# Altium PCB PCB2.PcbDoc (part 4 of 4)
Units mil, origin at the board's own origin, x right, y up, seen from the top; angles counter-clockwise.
Board outline 7170.03 x 5785.03 mil, 4 copper layers (Top Layer, GND, PWR, Bottom Layer), stack 22.378 mil thick; 348 components, 320 nets, 1937 pads, 429 vias.
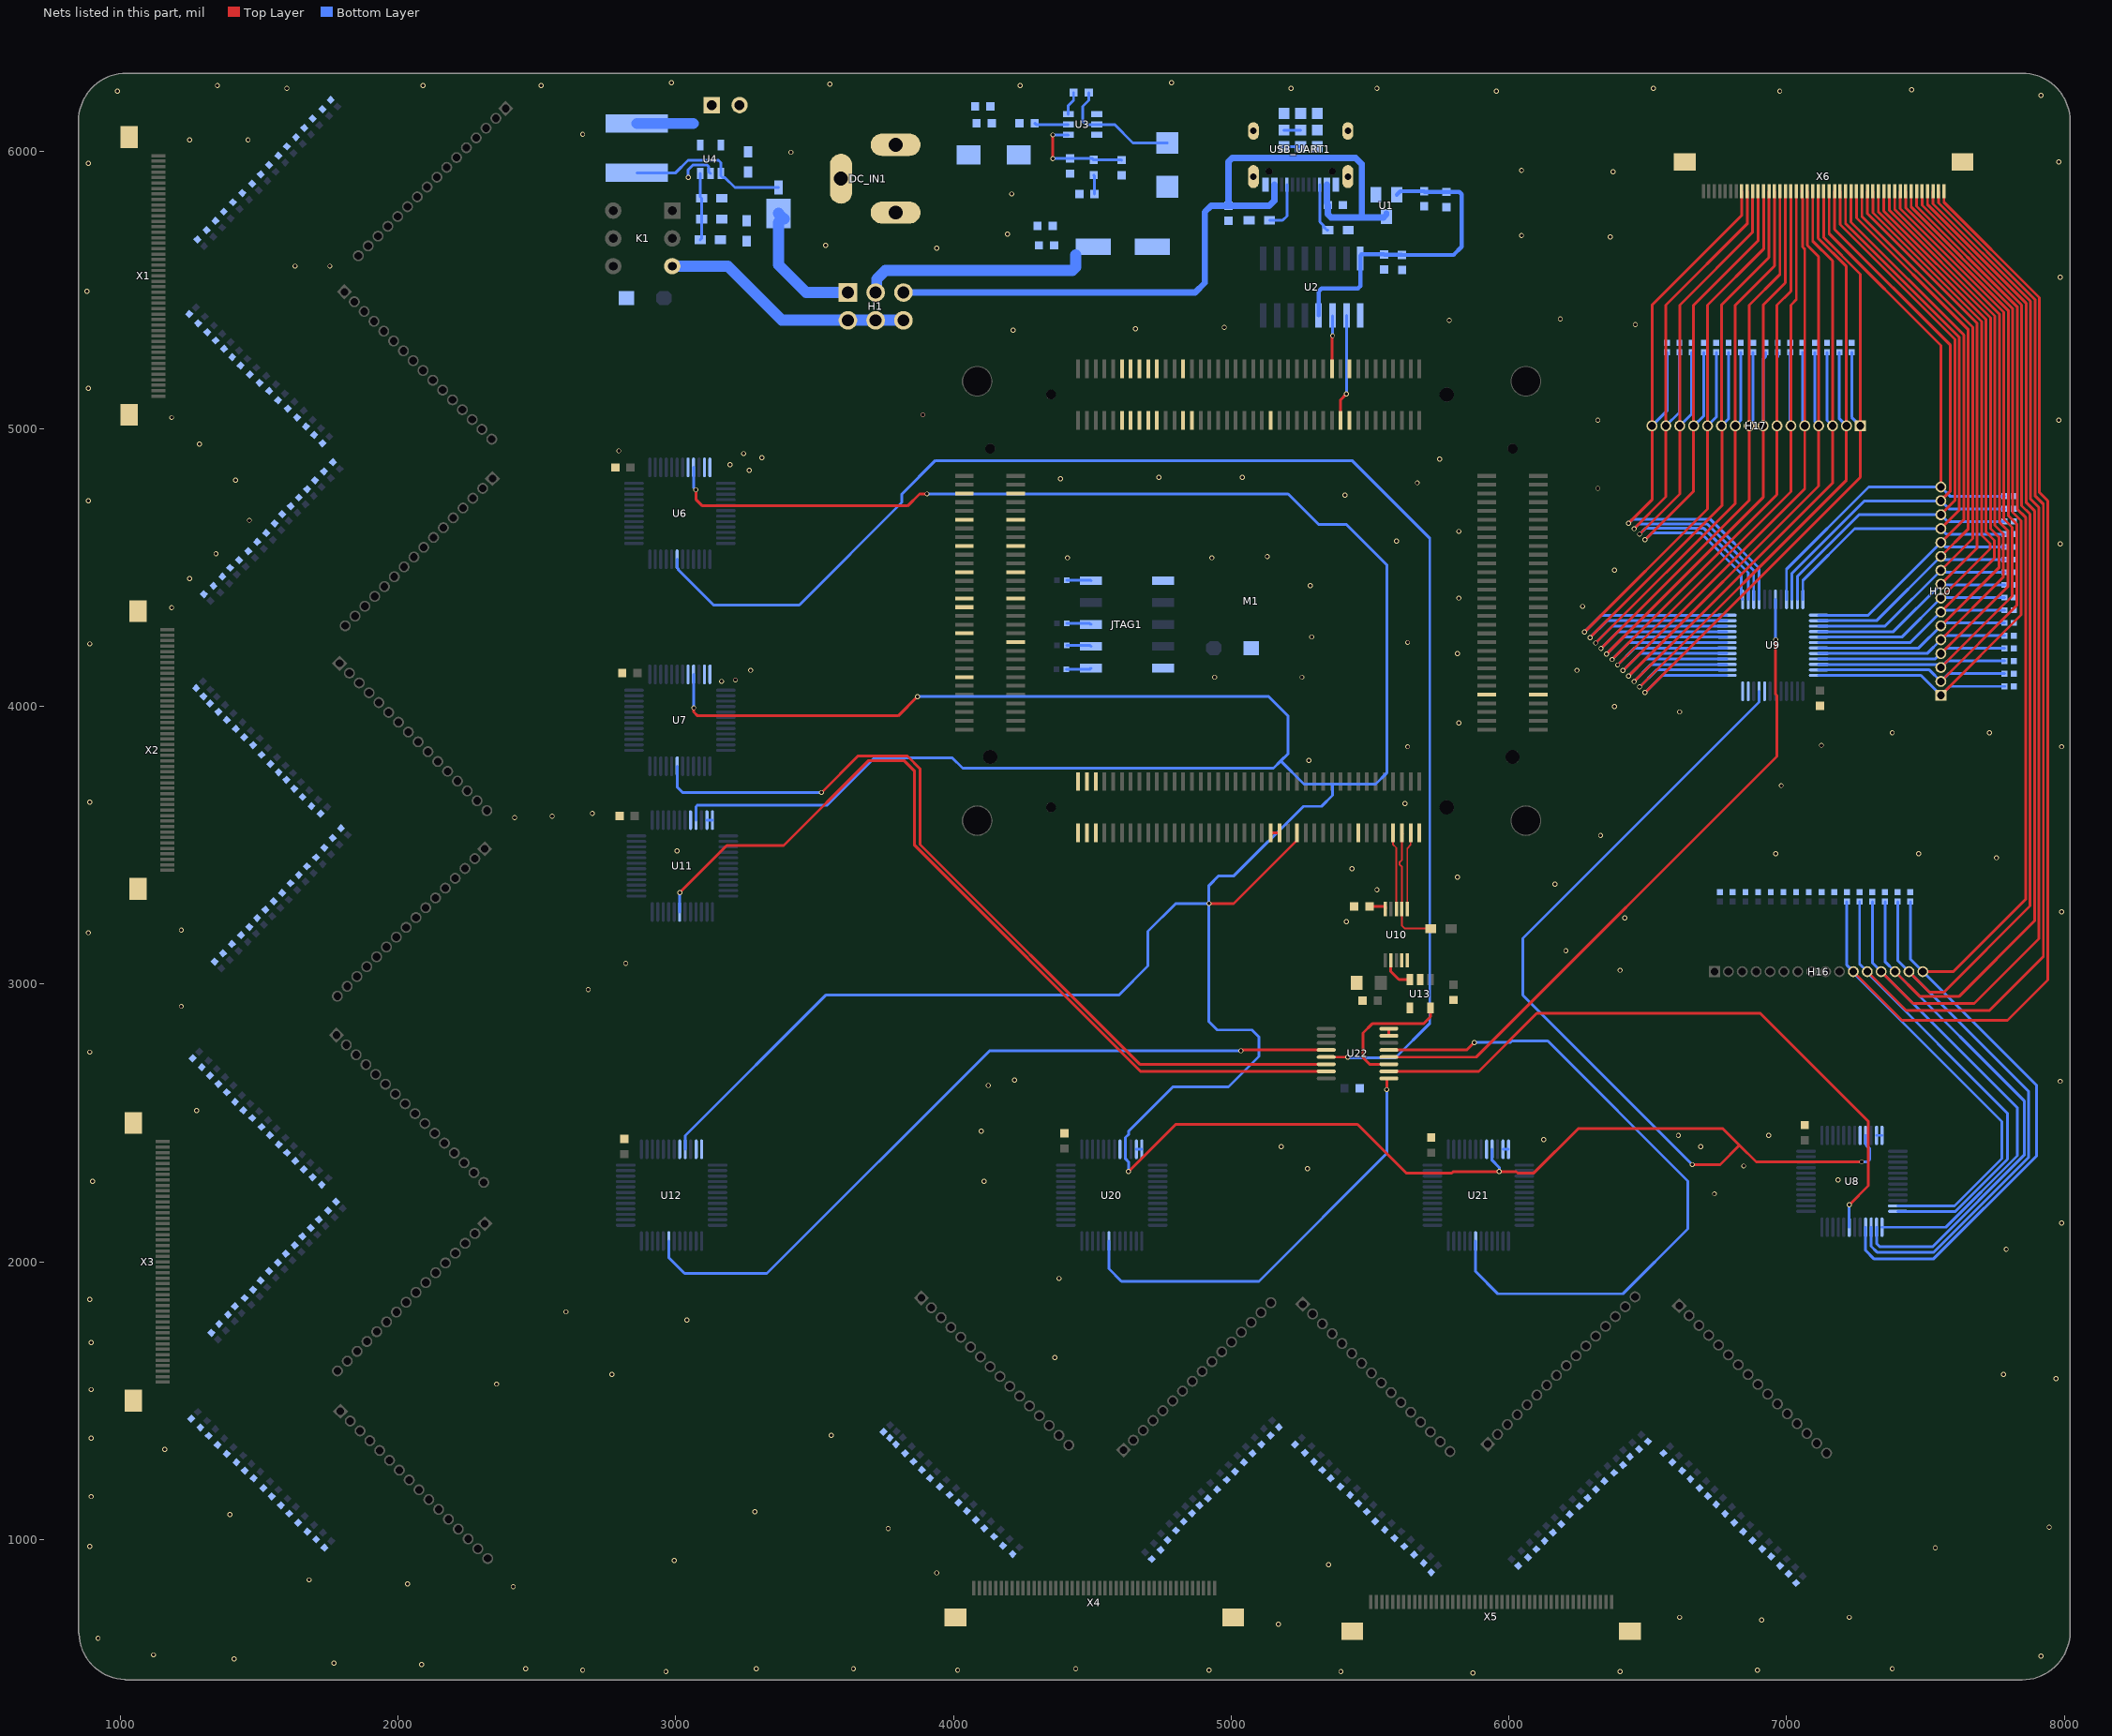
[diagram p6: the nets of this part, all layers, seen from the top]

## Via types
v1: diameter 18, hole 12, Top Layer to Bottom Layer, 429 vias

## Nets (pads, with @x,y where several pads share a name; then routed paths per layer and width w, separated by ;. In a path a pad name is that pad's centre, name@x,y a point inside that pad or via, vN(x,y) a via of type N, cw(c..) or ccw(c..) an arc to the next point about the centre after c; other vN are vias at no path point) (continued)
G218: H16.11 R194.2 U8.35 X6.1 | length 5428.8
  Top Layer w10: H16.11@7240,3045 7415,2870 7795,2870 7940,3015 7940,4740 7909.69,4770.31 7909.69,5472.1 7566.18,5815.6 X6.1@7566.18,5855
  Bottom Layer w10: R194.2@7216.75,3296.87 7216.75,3068.25 H16.11@7240,3045 7240,3039.77 7775,2504.77 7775,2372 7604.42,2201.42 U8.35@7400.36,2201.42
G219: H16.12 R196.2 U8.36 X6.2 | length 5305.2
  Top Layer w10: H16.12@7290,3045 7430,2905 7730,2905 7924,3099 7924,4728.17 7893.69,4758.48 7893.69,5465.47 7546.5,5812.66 X6.2@7546.5,5855.06
  Bottom Layer w10: R196.2@7262.44,3296.87 7262.44,3072.56 H16.12@7290,3045 7290,3040 7795,2535 7795,2369.37 7607.36,2181.73 U8.36@7400.36,2181.73
G220: H16.13 R198.2 U8.37 X6.3 | length 5286.6
  Top Layer w10: H16.13@7340,3045 7455,2930 7675,2930 7908,3163 7908,4716.32 7877.69,4746.64 7877.69,5458.84 7526.81,5809.72 X6.3@7526.81,5855
  Bottom Layer w10: R198.2@7308.14,3296.87 7308.14,3076.86 H16.13@7340,3045 7830,2555 7830,2381.74 7572.9,2124.64 U8.37@7343.27,2124.64
G221: H16.14 R200.2 U8.38 X6.4 | length 5290.4
  Top Layer w10: H16.14@7390,3045 7480,2955 7620,2955 7892,3227 7892,4704.49 7861.69,4734.81 7861.69,5452.22 7507.13,5806.77 X6.4@7507.13,5855
  Bottom Layer w10: U8.38@7323.58,2124.64 7323.58,2066.42 7335,2055 7525.89,2055 7855,2384.11 7855,2580 H16.14@7390,3045 7353.83,3081.17 R200.2@7353.83,3296.87
G222: H16.15 R202.2 U8.39 X6.5 | length 5231.8
  Top Layer w10: H16.15@7440,3045 7514,2971 7566,2971 7876,3281 7876,4692.64 7845.69,4722.96 7845.69,5445.59 7487.44,5803.83 X6.5@7487.44,5855
  Bottom Layer w10: U8.39@7303.9,2124.64 7303.9,2056.1 7325,2035 7530,2035 7871,2376 7871,2614 H16.15@7440,3045 7399.52,3085.48 R202.2@7399.52,3296.87
G223: H16.16 R204.2 U8.40 X6.6 | length 5159.7
  Top Layer w10: X6.6@7467.76,5855 7467.76,5800.89 7829.69,5438.96 7829.69,4711.13 7860,4680.81 7860,3305 7600,3045 H16.16@7490,3045
  Bottom Layer w10: U8.40@7284.21,2124.64 7284.21,2040.79 7315,2010 7527.63,2010 7900,2382.37 7900,2635 H16.16@7490,3045 7445.21,3089.79 R204.2@7445.21,3296.87
G224: H10.1 R206.2 U9.12 X6.7 | length 2810.4
  Top Layer w10: X6.7@7448.07,5855 7448.07,5797.95 7813.69,5432.33 7813.69,4699.28 7844,4668.97 7844,4329 H10.1@7555,4040
  Bottom Layer w10: U9.12@7115.36,4111.73 7483.27,4111.73 H10.1@7555,4040 7587.04,4072.04 R206.2@7784.05,4072.04
G225: H10.2 R208.2 U9.11 X6.8 | length 2740.9
  Top Layer w10: X6.8@7428.39,5855 7428.39,5795 7797.69,5425.71 7797.69,4687.45 7828,4657.14 7828,4363 H10.2@7555,4090
  Bottom Layer w10: U9.11@7115.36,4131.42 7513.58,4131.42 H10.2@7555,4090 7582.7,4117.7 R208.2@7784.05,4117.7
G226: H10.3 R210.2 U9.10 X6.9 | length 2671.5
  Top Layer w10: X6.9@7408.7,5855 7408.7,5792.06 7781.69,5419.08 7781.69,4675.6 7812,4645.29 7812,4397 H10.3@7555,4140
  Bottom Layer w10: U9.10@7115.36,4151.1 7543.9,4151.1 H10.3@7555,4140 7578.37,4163.37 R210.2@7784.05,4163.37
G227: H10.4 R212.2 U9.9 X6.10 | length 2617.9
  Top Layer w10: X6.10@7389.02,5855 7389.02,5789.12 7765.69,5412.45 7765.69,4663.77 7796,4633.46 7796,4431 H10.4@7555,4190
  Bottom Layer w10: U9.9@7115.36,4170.79 7534.46,4170.79 7553.67,4190 H10.4@7555,4190 7574.04,4209.04 R212.2@7784.05,4209.04
G228: H10.5 R214.2 U9.8 X6.11 | length 2573.6
  Top Layer w10: X6.11@7369.33,5855 7369.33,5786.18 7749.69,5405.82 7749.69,4651.93 7780,4621.61 7780,4465 H10.5@7555,4240
  Bottom Layer w10: U9.8@7115.36,4190.47 7505.47,4190.47 H10.5@7555,4240 7569.7,4254.7 R214.2@7784.05,4254.7
G229: H10.6 R216.2 U9.7 X6.12 | length 2529.3
  Top Layer w10: X6.12@7349.65,5855 7349.65,5783.23 7733.69,5399.2 7733.69,4640.1 7764,4609.78 7764,4499 H10.6@7555,4290
  Bottom Layer w10: U9.7@7115.36,4210.16 7475.16,4210.16 H10.6@7555,4290 7565.37,4300.37 R216.2@7784.05,4300.37
G230: H10.7 R218.2 U9.6 X6.13 | length 2484.9
  Top Layer w10: X6.13@7329.96,5855 7329.96,5780.29 7717.69,5392.57 7717.69,4628.25 7748,4597.93 7748,4533 H10.7@7555,4340
  Bottom Layer w10: U9.6@7115.36,4229.84 7444.84,4229.84 H10.7@7555,4340 7561.04,4346.04 R218.2@7784.05,4346.04
G231: H10.8 R220.2 U9.5 X6.14 | length 2440.6
  Top Layer w10: X6.14@7310.28,5855 7310.28,5777.35 7701.69,5385.94 7701.69,4616.42 7732,4586.1 7732,4567 H10.8@7555,4390
  Bottom Layer w10: U9.5@7115.36,4249.53 7414.53,4249.53 H10.8@7555,4390 7556.7,4391.7 R220.2@7784.05,4391.7
G232: H10.9 R222.2 U9.4 X6.15 | length 2373.3
  Top Layer w10: X6.15@7290.59,5855 7290.59,5774.41 7685.69,5379.31 7685.69,4570.69 H10.9@7555,4440
  Bottom Layer w10: U9.4@7115.36,4269.21 7384.21,4269.21 H10.9@7555,4440 7557.63,4437.37 R222.2@7784.05,4437.37
G233: H10.10 R224.2 U9.3 X6.16 | length 2332.6
  Top Layer w10: X6.16@7270.91,5855 7270.91,5764.09 7669.69,5365.31 7669.69,4604.69 H10.10@7555,4490
  Bottom Layer w10: U9.3@7115.36,4288.9 7353.9,4288.9 H10.10@7555,4490 7561.96,4483.04 R224.2@7784.05,4483.04
G234: H10.11 R226.2 U9.2 X6.17 | length 2291.8
  Top Layer w10: X6.17@7251.22,5855 7251.22,5758.78 7653.69,5356.31 7653.69,4638.69 H10.11@7555,4540
  Bottom Layer w10: U9.2@7115.36,4308.58 7323.58,4308.58 H10.11@7555,4540 7566.3,4528.7 R226.2@7784.05,4528.7
G235: H10.12 R228.2 U9.1 X6.18 | length 2251.1
  Top Layer w10: X6.18@7231.54,5855 7231.54,5743.46 7637.69,5337.31 7637.69,4672.69 H10.12@7555,4590
  Bottom Layer w10: U9.1@7115.36,4328.27 7293.27,4328.27 H10.12@7555,4590 7570.63,4574.37 R228.2@7784.05,4574.37
G236: H10.13 R230.2 U9.48 X6.19 | length 2291.7
  Top Layer w10: X6.19@7211.85,5855 7211.85,5738.15 7621.69,5328.31 7621.69,4707.63 7555,4640.95 H10.13@7555,4640
  Bottom Layer w10: U9.48@7058.27,4385.36 7058.27,4453.27 7245,4640 H10.13@7555,4640 7574.96,4620.04 R230.2@7784.05,4620.04
G237: H10.14 R232.2 U9.47 X6.20 | length 2287.8
  Top Layer w10: X6.20@7192.17,5855 7192.17,5735.2 7605.69,5321.69 7605.69,4741.63 7555,4690.95 H10.14@7555,4690
  Bottom Layer w10: U9.47@7038.58,4385.36 7038.58,4468.58 7260,4690 H10.14@7555,4690 7579.3,4665.7 R232.2@7784.05,4665.7
G238: H10.15 R234.2 U9.46 X6.21 | length 2285.5
  Top Layer w10: X6.21@7172.48,5855 7172.48,5717.52 7589.69,5300.31 7589.69,4775.63 7569.37,4755.31 7561.48,4755.31 7561.48,4746.48 H10.15@7555,4740
  Bottom Layer w10: U9.46@7018.9,4385.36 7018.9,4478.9 7280,4740 H10.15@7555,4740 7583.63,4711.37 R234.2@7784.05,4711.37
G239: H10.16 R236.2 U9.45 X6.22 | length 2261.5
  Top Layer w10: X6.22@7152.8,5855 7152.8,5702.2 7555,5300 H10.16@7555,4790
  Bottom Layer w10: U9.45@6999.21,4385.36 6999.21,4494.21 7295,4790 H10.16@7555,4790 7587.96,4757.04 R236.2@7784.05,4757.04
G240: H17.1 R238.2 U9.25 X6.23 | length 2778.6
  Top Layer w10: v1(6490,4050) 7265,4825 H17.1@7265,5010 7265,5556.55 7133.11,5688.44 X6.23@7133.11,5855
  Bottom Layer w10: v1(6490,4050) 6551.73,4111.73 U9.25@6784.64,4111.73 ; R238.2@7233.96,5274.85 7233.96,5041.04 H17.1@7265,5010
G241: H17.2 R240.2 U9.26 X6.24 | length 2751.1
  Top Layer w10: v1(6470.2,4069.8) 7215,4814.6 H17.2@7215,5010 7215,5583.92 7113.43,5685.49 X6.24@7113.43,5855
  Bottom Layer w10: v1(6470.2,4069.8) 6531.82,4131.42 U9.26@6784.64,4131.42 ; R240.2@7189.63,5274.85 7189.63,5035.37 H17.2@7215,5010
G242: H17.3 R242.2 U9.27 X6.25 | length 2723.6
  Top Layer w10: v1(6450.4,4089.6) 7165,4804.19 H17.3@7165,5010 7165,5604.08 7093.74,5675.33 X6.25@7093.74,5855
  Bottom Layer w10: v1(6450.4,4089.6) 6511.9,4151.1 U9.27@6784.64,4151.1 ; R242.2@7145.3,5274.85 7145.3,5029.7 H17.3@7165,5010
G243: H17.4 R244.2 U9.28 X6.26 | length 2696.2
  Top Layer w10: v1(6430.6,4109.4) 7115,4793.79 H17.4@7115,5010 7115,5619.24 7074.06,5660.17 X6.26@7074.06,5855
  Bottom Layer w10: v1(6430.6,4109.4) 6492,4170.79 U9.28@6784.64,4170.79 ; R244.2@7100.96,5274.85 7100.96,5024.04 H17.4@7115,5010
G244: H17.5 R246.2 U9.29 X6.27 | length 2668.7
  Top Layer w10: v1(6410.8,4129.2) 7065,4783.39 H17.5@7065,5010 7065,5646.61 7057.15,5654.45 7057.15,5828.55 7055.28,5830.43 7055.28,5854.09 X6.27@7054.37,5855
  Bottom Layer w10: v1(6410.8,4129.2) 6472.08,4190.47 U9.29@6784.64,4190.47 ; R246.2@7056.63,5274.85 7056.63,5018.37 H17.5@7065,5010
G245: H17.6 R248.2 U9.30 X6.28 | length 2657.6
  Top Layer w10: v1(6391.01,4148.99) 7015,4772.99 H17.6@7015,5010 7015,5445 7034.69,5464.69 X6.28@7034.69,5855
  Bottom Layer w10: v1(6391.01,4148.99) 6452.17,4210.16 U9.30@6784.64,4210.16 ; R248.2@7012.3,5274.85 7012.3,5012.7 H17.6@7015,5010
G246: H17.7 R250.2 U9.31 X6.29 | length 2657.7
  Top Layer w10: v1(6371.21,4168.79) 6965,4762.59 H17.7@6965,5010 6965,5445 7015,5495 X6.29@7015,5855
  Bottom Layer w10: v1(6371.21,4168.79) 6432.25,4229.84 U9.31@6784.64,4229.84 ; H17.7@6965,5010 6965,5255.75 6967.96,5258.72 R250.2@6967.96,5274.85
G247: H17.8 R252.2 U9.32 X6.30 | length 2660
  Top Layer w10: v1(6351.41,4188.59) 6915,4752.19 H17.8@6915,5010 6915,5445 6995.32,5525.32 X6.30@6995.32,5855
  Bottom Layer w10: v1(6351.41,4188.59) 6412.34,4249.53 U9.32@6784.64,4249.53 ; H17.8@6915,5010 6915,5250.09 6923.63,5258.72 R252.2@6923.63,5274.85
G248: H17.9 R254.2 U9.33 X6.31 | length 2662.4
  Top Layer w10: v1(6331.61,4208.39) 6865,4741.78 H17.9@6865,5010 6865,5445 6975.63,5555.63 X6.31@6975.63,5855
  Bottom Layer w10: v1(6331.61,4208.39) 6392.43,4269.21 U9.33@6784.64,4269.21 ; H17.9@6865,5010 6879.3,5024.3 R254.2@6879.3,5274.85
G249: H17.10 R256.2 U9.34 X6.32 | length 2664.7
  Top Layer w10: v1(6311.81,4228.19) 6815,4731.38 H17.10@6815,5010 6815,5445 6955.95,5585.95 X6.32@6955.95,5855
  Bottom Layer w10: v1(6311.81,4228.19) 6372.52,4288.9 U9.34@6784.64,4288.9 ; H17.10@6815,5010 6834.96,5029.96 R256.2@6834.96,5274.85
G250: H17.11 R258.2 U9.35 X6.33 | length 2668.7
  Top Layer w10: v1(6292.01,4247.99) 6767.01,4722.99 6767.01,5007.99 H17.11@6765,5010 6765,5445 6936.26,5616.26 X6.33@6936.26,5855
  Bottom Layer w10: v1(6292.01,4247.99) 6352.6,4308.58 U9.35@6784.64,4308.58 ; H17.11@6765,5010 6790.63,5035.63 R258.2@6790.63,5274.85
G251: H17.12 R260.2 U9.36 X6.34 | length 2669.4
  Top Layer w10: v1(6272.21,4267.79) 6715,4710.58 H17.12@6715,5010 6715,5445 6916.58,5646.58 X6.34@6916.58,5855
  Bottom Layer w10: v1(6272.21,4267.79) 6332.69,4328.27 U9.36@6784.64,4328.27 ; H17.12@6715,5010 6746.3,5041.3 R260.2@6746.3,5274.85
G252: H17.13 R262.2 U9.37 X6.35 | length 2216.5
  Top Layer w10: v1(6490,4600) 6665,4775 H17.13@6665,5010 6665,5445 6896.89,5676.89 X6.35@6896.89,5855
  Bottom Layer w10: v1(6490,4600) 6515,4625 6690,4625 6836.73,4478.27 6836.73,4390.36 U9.37@6841.73,4385.36 ; H17.13@6665,5010 6701.96,5046.96 R262.2@6701.96,5274.85
G253: H17.14 R264.2 U9.38 X6.36 | length 2248.5
  Top Layer w10: v1(6470.2,4619.8) 6615,4764.6 H17.14@6615,5010 6615,5445 6877.21,5707.21 X6.36@6877.21,5855
  Bottom Layer w10: v1(6470.2,4619.8) 6491.4,4641 6701.85,4641 6861.42,4481.43 U9.38@6861.42,4385.36 ; H17.14@6615,5010 6657.63,5052.63 R264.2@6657.63,5274.85
G254: H17.15 R266.2 U9.39 X6.37 | length 2280.4
  Top Layer w10: v1(6450.4,4639.6) 6565,4754.2 H17.15@6565,5010 6565,5445 6857.52,5737.52 X6.37@6857.52,5855
  Bottom Layer w10: v1(6450.4,4639.6) 6467.8,4657 6713.68,4657 6881.1,4489.58 U9.39@6881.1,4385.36 ; H17.15@6565,5010 6613.3,5058.3 R266.2@6613.3,5274.85
G255: H17.16 R268.2 U9.40 X6.38 | length 2312.3
  Top Layer w10: v1(6430.6,4659.4) 6515,4743.8 H17.16@6515,5010 6515,5445 6837.84,5767.84 X6.38@6837.84,5855
  Bottom Layer w10: v1(6430.6,4659.4) 6444.21,4673 6725.52,4673 6900.79,4497.73 U9.40@6900.79,4385.36 ; H17.16@6515,5010 6568.96,5063.96 R268.2@6568.96,5274.85
Gate: U10.2 U13.3 | length 120.2
  Top Layer w10: U10.2@5574.72,3085.55 5574.72,3045.28 5603.81,3016.18 U13.3@5642.6,3016.18
Gate1: U13.5 U22.3 | length 490.1
  Top Layer w10: U22.3@5567.82,2711.61 5498.39,2711.61 5474.74,2735.26 5474.74,2824.43 5507.64,2857.32 5692.32,2857.32 5717.4,2882.4 U13.5@5717.4,2913.82
Gate2-1: U6.43 U22.13 | length 5316.7
  Top Layer w10: U22.13@5342.18,2737.21 v1@5419.79,2737.21
  Bottom Layer w10: U6.43@3005.16,4529.64 3005.16,4499.45 3008.33,4496.28 3008.33,4492.88 3136.21,4365 3445,4365 3814,4734 3814,4764 3935,4885 5435,4885 5715,4605 5715,2858.94 5591.06,2735 v1@5420,2735
  other v1: 5420,2737
Gate2-2: U7.43 U22.14 | length 3093.5
  Top Layer w10: v1(3525,3690) 3656,3821 3834,3821 3880,3775 3880,3502.37 4670.76,2711.61 U22.14@5342.18,2711.61
  Bottom Layer w10: U7.43@3005.16,3784.64 3005.16,3709.84 3025,3690 v1(3525,3690)
Gate2-3: U11.43 U22.15 | length 3214.1
  Top Layer w10: v1(3015,3330) 3184,3499 3389,3499 3695,3805 3821.63,3805 3860,3766.63 3860,3499.75 4673.73,2686.02 U22.15@5342.18,2686.02
  Bottom Layer w10: U11.43@3014.06,3260 3014.06,3329.06 v1(3015,3330)
Gate2-4: U12.43 U22.12 | length 2783.7
  Top Layer w10: v1(5035,2760) 5037.16,2760 5039.96,2762.8 U22.12@5342.18,2762.8
  Bottom Layer w10: U12.43@2975.16,2074.64 2975.16,2014.84 3032,1958 3328,1958 4130,2760 v1(5035,2760)
Gate2-5: U20.43 U22.1 | length 1586
  Top Layer w10: v1(5560,2620) 5560,2658.81 5561.62,2660.43 U22.1@5567.82,2660.43
  Bottom Layer w10: U20.43@4560.16,2074.64 4560.16,1974.84 4605,1930 5099.97,1930 5560,2390.03 v1(5560,2620)
Gate2-6: U21.43 U22.5 | length 2473.9
  Top Layer w10: U22.5@5567.82,2762.8 5847.8,2762.8 v1(5875,2790)
  Bottom Layer w10: v1(5875,2790) 6006.08,2790 6011.08,2795 6140,2795 6644,2291 6644,2119 6410,1885 5960,1885 5880.16,1964.84 U21.43@5880.16,2074.64
Gate2-7: U8.43 U22.2 | length 2383.7
  Top Layer w10: U22.2@5567.82,2686.02 5891.02,2686.02 6100,2895 6905,2895 7294,2506 7294,2274 v1(7225.16,2205.16)
  Bottom Layer w10: U8.43@7225.16,2124.64 v1(7225.16,2205.16)
Gate2-8: U9.43 U22.4 | length 2413.2
  Top Layer w10: U22.4@5567.82,2737.21 5882.21,2737.21 6965,3820 6965,4038.92 6960,4043.92 v1(6960,4240)
  Bottom Layer w10: U9.43@6959.84,4385.36 6959.92,4385.28 6959.92,4240.08 v1(6960,4240)
GND: Battery1.2 C1.1 C2.1 C3.1 C4.1 C5.2 C6.2 C9.2 C10.2 C11.2 C12.1 C13.1 C14.2 C16.2 C17.1 C20.2 C21.2 C22.2 C23.2 C24.1 C25.1 C26.2 C27.2 C29.2 C30.2 C31.2 D3.1 D4.1 DC_IN1.2 DC_IN1.3 E1.2 JTAG1.2 JTAG1.10 M1.J1_51 M1.J1_52 M1.J2_11 M1.J2_12 M1.J2_13 M1.J2_14 M1.J2_15 M1.J2_16 M1.J2_17 M1.J2_18 M1.J2_19 M1.J2_20 M1.J2_25 M1.J2_26 M1.J2_28 M1.J2_46 M1.J2_63 M1.J2_64 M1.J3_5 M1.J3_6 M1.J3_11 M1.J3_12 M1.J3_17 M1.J3_18 M1.J3_23 M1.J3_24 M1.J3_29 M1.J3_30 M1.J3_32 M1.J3_38 M1.J3_39 M1.J3_48 M1.J4_1 M1.J4_2 M1.J4_3 M1.J4_4 M1.J4_5 M1.J4_6 M1.J4_46 M1.J4_48 M1.J4_66 M1.J4_80 R5.2 R6.2 R10.2 R12.1 R13.1 R14.1 R15.1 R16.1 R17.1 R18.1 R19.1 R20.1 R21.1 R22.1 R23.1 R24.1 R25.1 R26.1 R27.1 R28.1 R29.1 R30.1 R31.1 R32.1 R33.1 R34.1 R35.1 R36.1 R37.1 R38.1 R39.1 R40.1 R41.1 R42.1 R43.1 R44.1 R45.1 R46.1 R47.1 R48.1 R49.1 R50.1 R51.1 R52.1 R53.1 R54.1 R55.1 R56.1 R57.1 R58.1 R59.1 R60.1 R61.1 R62.1 R63.1 R64.1 R65.1 R66.1 R67.1 R68.1 R69.1 R70.1 R71.1 R72.1 R73.1 R74.1 R75.1 R76.1 R77.1 R78.1 R79.1 R80.1 R81.1 R82.1 R83.1 R84.1 R85.1 R86.1 R87.1 R88.1 R89.1 R90.1 R91.1 R92.1 R93.1 R94.1 R95.1 R96.1 R97.1 R98.1 R99.1 R100.1 R101.1 R102.1 R103.1 R104.1 R105.1 R106.1 R107.1 R108.1 R109.1 R110.1 R111.1 R112.1 R113.1 R114.1 R115.1 R116.1 R117.1 R118.1 R119.1 R120.1 R121.1 R122.1 R123.1 R124.1 R125.1 R126.1 R127.1 R128.1 R129.1 R130.1 R131.1 R132.1 R133.1 R134.1 R135.1 R136.1 R137.1 R139.1 R140.1 R141.1 R142.1 R143.1 R144.1 R145.1 R146.1 R147.1 R148.1 R149.1 R150.1 R151.1 R152.1 R153.1 R154.1 R155.1 R156.1 R157.1 R158.1 R159.1 R160.1 R161.1 R162.1 R163.1 R164.1 R165.1 R166.1 R167.1 R168.1 R169.1 R170.1 R171.1 R172.1 R173.1 R174.1 R175.1 R176.1 R177.1 R178.1 R179.1 R180.1 R181.1 R182.1 R183.1 R184.1 R185.1 R186.1 R187.1 R188.1 R189.1 R190.1 R191.1 R192.1 R193.1 R194.1 R195.1 R196.1 R197.1 R198.1 R199.1 R200.1 R201.1 R202.1 R203.1 R204.1 R205.1 R206.1 R207.1 R208.1 R209.1 R210.1 R211.1 R212.1 R213.1 R214.1 R215.1 R216.1 R217.1 R218.1 R219.1 R220.1 R221.1 R222.1 R223.1 R224.1 R225.1 R226.1 R227.1 R228.1 R229.1 R230.1 R231.1 R232.1 R233.1 R234.1 R235.1 R236.1 R237.1 R238.1 R239.1 R240.1 R241.1 R242.1 R243.1 R244.1 R245.1 R246.1 R247.1 R248.1 R249.1 R250.1 R251.1 R252.1 R253.1 R254.1 R255.1 R256.1 R257.1 R258.1 R259.1 R260.1 R261.1 R262.1 R263.1 R264.1 R265.1 R266.1 R267.1 R268.1 R269.1 U1.1 U2.1 U3.1 U4.2 U6.20 U6.23 U6.24 U7.20 U7.23 U7.24 U8.20 U8.23 U8.24 U9.20 U9.23 U9.24 U10.4 U10.5 U11.20 U11.23 U11.24 U12.20 U12.23 U12.24 U13.2 U13.4 U20.20 U20.23 U20.24 U21.20 U21.23 U21.24 U22.7 U22.8 USB_UART1.1 USB_UART1.12 USB_UART1.SH1 USB_UART1.SH2 USB_UART1.SH3 USB_UART1.SH4 X1.46 X1.47 X2.46 X2.47 X3.46 X3.47 X4.46 X4.47 X5.46 X5.47 X6.46 X6.47 | length 394.3
  Top Layer w10: M1.J4_46@5141.97,3544.25 M1.J4_48@5173.46,3544.25 ; U22.7@5567.82,2813.98 U22.8@5567.82,2839.57
  Bottom Layer w10: v1(3045,5905) 3045,5932.37 3062.63,5950 3112.33,5950 3118.19,5944.14 3118.19,5925.63 U4.2@3125,5918.81 ; U11.23@3112.48,3590.71 U11.24@3132.17,3590.71 ; U20.23@4658.58,2405.36 U20.24@4678.27,2405.36 ; USB_UART1.SH2@5190,6015 USB_UART1.SH2@5250,6015 ; USB_UART1.SH2@5190,6075 USB_UART1.SH2@5250,6075 ; U21.23@5978.58,2405.36 U21.24@5998.27,2405.36 ; U8.23@7323.58,2455.36 U8.24@7343.27,2455.36
  other v1: 5870,520 2965,525 5395,525 6400,525 2665,530 4015,530 4920,530 6895,530 2460,535 3290,535 3640,535 4440,535 7380,535 2085,550 1770,555 1410,570 7915,580 1120,585 920,645 5170,695 6910,710 6615,720 7225,720 2415,830 2035,840 1680,855 3940,880 5350,910 2995,925 7535,970 890,975 3765,1040 7945,1045 1395,1090 3285,1100 895,1155 1160,1325 895,1365 3560,1375 895,1540 2355,1560 7970,1580 2770,1595 7780,1595 4365,1655 895,1710 3040,1790 2605,1820 890,1865 4380,1940 7790,2045 7990,2140 6740,2245 900,2290 4110,2290 7185,2295 5275,2335 6845,2345 5180,2415 6690,2415 6125,2440 6610,2455 6935,2455 4100,2470 1275,2545 4125,2635 7985,2650 4220,2655 890,2755 1220,2920 2685,2980 6400,3050 2820,3075 6205,3120 885,3185 1220,3195 5415,3225 6416.97,3238.03 7990,3260 5525,3340 6165,3360 5815,3385 5435,3415 7755,3455 6960,3470 7475,3470 3005,3480 6330,3535 2420,3600 2555,3605 2700,3615 5625,3650 890,3655 6980,3715 5280,3805 5635,3855 7990,3855 7125,3860 7380,3905 7730,3905 5820,3940 6615,3980 6380,4000 3165,4090 3215,4095 4940,4105 5255,4105 3270,4130 6245,4130 5815,4190 890,4225 5635,4230 5290,4250 1185,4355 6265,4360 5820,4390 5285,4435 1250,4460 6380,4490 4410,4535 4930,4535 5130,4540 1345,4550 7985,4585 5595,4595 5820,4630 1465,4670 885,4740 5410,4760 6320,4785 5670,4805 1415,4815 4385,4820 4740,4825 5040,4825 3265,4850 3195,4870 5750,4890 3310,4895 3245,4910 2795,4920 1285,4945 6320,5030 7980,5030 1185,5040 3890,5050 885,5145 4215,5355 4655,5360 4975,5365 6455,5375 5785,5390 6185,5395 880,5495 7985,5545 1630,5585 1755,5585 3940,5650 3540,5660 6365,5690 6045,5695 4195,5700 4210,5845 6375,5925 6045,5930 885,5955 7980,5960 3415,5995 1250,6040 1460,6040 2665,6060 7915,6200 990,6215 5955,6215 6975,6215 7450,6220 1600,6225 5215,6225 5525,6225 6520,6225 1350,6235 2090,6235 2515,6235 4240,6235 3555,6240 2985,6245 4785,6245
NetBattery1_1: Battery1.1 C16.1 L2.1 U4.4 U4.5 | length 203.6
  Bottom Layer w40: L2.1@2860,6098.58 3063.58,6098.58
NetC7_1: C7.1 L1.1 U3.2 | length 450.7
  Bottom Layer w10: C7.1@4487,6210 4487,6182 4465,6160 4465,6105 4475,6095 U3.2@4516.18,6095 4580,6095 4646.26,6028.74 L1.1@4770,6028.74
NetC7_2: C7.2 U3.6 | length 85.3
  Bottom Layer w10: U3.6@4413.82,6132.4 4413.82,6163.82 4432.5,6182.5 C7.2@4432.5,6209.94
NetC8_2: C8.2 R7.1 | length 69
  Bottom Layer w10: R7.1@4505,5913 4507.5,5910.5 C8.2@4507.5,5845.06
NetC12_2: C12.2 C13.2 D1.2 R8.1 U3.3
NetC15_2: C15.2 R11.1 R12.2 U4.3 | length 243.3
  Bottom Layer w10: U4.3@3087.6,5918.81 3087.6,5835.9 C15.2@3093.5,5830 R11.1@3093.5,5755 3093.5,5685 R12.2@3088.5,5680
NetC17_2: C17.2 U10.10 | length 66.3
  Top Layer w10: C17.2@5497.5,3279.94 5554.13,3279.94 5555.03,3279.03 U10.10@5555.03,3270.59
NetD1_1: D1.1 DC_IN1.1
NetD2_2: D2.2 L2.2 U4.1 | length 596.3
  Bottom Layer w10: L2.2@2860,5921.42 3000.1,5921.42 3044.69,5966 3154,5966 3162.4,5957.6 U4.1@3162.4,5918.81 3162.4,5910.94 3169.21,5904.13 3177.09,5904.13 3212.91,5868.31 D2.2@3370.06,5868.31
NetJTAG1_1: JTAG1.1 R1.2 | length 89.5
  Bottom Layer w10: R1.2@4407,4134 4491.56,4134 JTAG1.1@4495.08,4137.52
NetJTAG1_3: JTAG1.3 R2.2 | length 88.2
  Bottom Layer w10: R2.2@4408,4219 4492.34,4219 JTAG1.3@4495.08,4216.26
NetJTAG1_5: JTAG1.5 R3.2 | length 88.7
  Bottom Layer w10: R3.2@4408,4299 4491.08,4299 JTAG1.5@4495.08,4295
NetJTAG1_9: JTAG1.9 R4.2 | length 87.7
  Bottom Layer w10: R4.2@4408,4454 4493.56,4454 JTAG1.9@4495.08,4452.48
NetR5_1: R5.1 USB_UART1.4 | length 181.6
  Bottom Layer w10: R5.1@5138,5750 5185,5750 5200.79,5765.79 USB_UART1.4@5200.79,5878.05
NetR6_1: R6.1 USB_UART1.10 | length 177.8
  Bottom Layer w10: USB_UART1.10@5318.9,5878.05 5318.9,5744.6 5333.5,5730 5333.5,5725.75 5344.25,5715 R6.1@5348.5,5715
NetR7_2: R7.2 R9.2 R10.1 U3.4 | length 391.1
  Top Layer w10: v1(4357.5,5972.5) v1(4357.5,6057.5)
  Bottom Layer w10: v1(4357.5,5972.5) R9.2@4419.94,5972.5 4499.94,5972.5 R7.2@4504.94,5967.5 4604.5,5967.5 R10.1@4605,5967 ; v1(4357.5,6057.5) v1(4357.5,6057.5) 4413.77,6057.55 U3.4@4413.82,6057.6
NetR8_2: R8.2 U3.5 | length 123.4
  Bottom Layer w10: R8.2@4292.5,6100.06 4297.56,6095 U3.5@4413.82,6095
SCL: M1.J4_78 U10.6 | length 284.1
  Top Layer w6.16: U10.6@5633.77,3270.59 5633.77,3379.68 5633.77,3395 5633.77,3405 5633.77,3410 5633.77,3488.77 5645.95,3500.95 M1.J4_78@5645.95,3544.25 M1.J4_78@5642.14,3540.44
SDA: M1.J4_74 U10.8 | length 283.8
  Top Layer w6.16: M1.J4_74@5586.76,3540.44 M1.J4_74@5582.95,3544.25 5582.95,3502.05 5594.41,3490.59 U10.8@5594.41,3270.59
SYNC: M1.J4_76 R138.1 U10.7 | length 454.7
  Top Layer w6.16: M1.J4_76@5618.15,3540.55 M1.J4_76@5614.45,3544.25 5614.09,3543.89 5614.09,3475 5614.09,3472.5 5614.09,3455 5614.09,3452.44 5614.09,3446.46 5610.49,3442.85 5609.81,3442.85 5606.57,3439.62 5606.57,3429.92 5609.81,3426.69 5610.49,3426.69 5614.09,3423.08 5614.09,3420 5614.09,3410 5614.09,3385 5614.09,3379.68 U10.7@5614.09,3270.59 5614.09,3210.91 5625,3200 R138.1@5718.5,3200
UART1_RXD: M1.J2_62 U2.2 | length 386.3
  Top Layer w10: M1.J2_62@5393.98,5030 5393.98,5103.98 v1(5415,5125)
  Bottom Layer w10: v1(5415,5125) U2.2@5415,5407.64
UART1_TXD: M1.J2_59 U2.3 | length 192.3
  Top Layer w10: M1.J2_59@5362.48,5215.04 5363.74,5216.3 5363.74,5333.74 v1(5365,5335)
  Bottom Layer w10: v1(5365,5335) U2.3@5365,5406.29
UART_3.3V: C2.2 C3.2 C5.1 C6.1 U1.2 U2.4 U2.16 | length 1166.7
  Bottom Layer w15: U2.4@5315,5407.64 5315,5495 5325,5505 5456.21,5505 5465,5513.79 U2.16@5465,5612.36 5465,5623.06 5469.31,5627.37 C6.1@5550.24,5627.37 5551.24,5626.37 5614.24,5626.37 C5.1@5615.24,5625.37 5800.37,5625.37 5830,5655 5830,5843.54 5821.21,5852.33 5697.14,5852.33 C3.2@5694.64,5854.83 5608.48,5854.83 U1.2@5595.98,5842.3
VBAT: C14.1 C15.1 D2.1 H1.1 R11.2 | length 497
  Bottom Layer w40: D2.1@3370,5775 3390,5755 3383.15,5755 3370,5741.85 3370,5590 3470,5490 H1.1@3620,5490
VBTN: C8.1 C9.1 C10.1 C11.1 H1.3 L1.2 R9.1 | length 827.6
  Bottom Layer w40: H1.3@3720,5490 3723.59,5493.59 3723.59,5538.59 3755,5570 4428.28,5570 4440,5581.72 4440,5625
VIN: H1.2 H1.4 H1.6 K1.3 | length 910.1
  Bottom Layer w40: K1.3@2990.71,5585 3187.6,5585 3381.3,5391.3 3620,5391.3 3720,5391.3 3818.7,5391.3 H1.6@3820,5390
VUSB: C1.2 C4.2 H1.5 U1.3 USB_UART1.2 USB_UART1.11 | length 2851.1
  Bottom Layer w20: U1.3@5548.57,5760 5558.57,5770 U1.3@5558.57,5776.41
  Bottom Layer w23: H1.5@3820,5490 4870,5490 4905,5525 4905,5780 4927.5,5802.5 C4.2@4989.94,5802.5 ; USB_UART1.2@5155.51,5878.05 5155.51,5820.51 5137.5,5802.5 C4.2@4989.94,5802.5 ; C1.2@5344.49,5812.95 USB_UART1.11@5344.49,5878.05 ; C1.2@5347.5,5804.94 5347.5,5771.72 5359.22,5760 5470,5760 ; U1.3@5548.57,5760 5470,5760 ; C4.2@4989.94,5802.5 4989.94,5961.53 5003.41,5975 5448.28,5975 5470,5953.28 5470,5760
WR: M1.J4_52 U6.21 U7.21 U8.21 U9.21 U11.21 U12.21 U20.21 U21.21 | length 19224
  Top Layer w10: v1(3065,3995) 3065,3980 3079,3966 3801,3966 v1(3870,4035) ; v1(3072.53,4780) 3072.53,4745.7 3096.17,4722.06 3835,4722.06 3877.94,4765 v1(3905,4765) ; v1(4630,2325) 4800,2495 5455,2495 5630,2320 5793.92,2320 5798.92,2325 6026.08,2325 6031.08,2320 6090,2320 6250,2480 6770,2480 6830,2420 ; v1(4920,3290) 5008.78,3290 5236.46,3517.68 M1.J4_52@5236.46,3544.25 ; v1(6660,2350) 6760,2350 6830,2420 ; v1(7270,2360) 6890,2360 6830,2420
  Bottom Layer w10: U12.21@3034.21,2405.36 3034.21,2454.21 3540,2960 4595,2960 4700,3065 4700,3190 4800,3290 v1(4920,3290) ; U7.21@3064.21,4115.36 3064.41,4115.16 3064.41,3995.59 v1(3065,3995) ; U6.21@3064.21,4860.36 3064.21,4788.32 v1(3072.53,4780) ; U11.21@3073.11,3590.71 3073.11,3639.14 3078.97,3645 3545,3645 3715,3815 3995.57,3815 4033.25,3777.32 5152.32,3777.32 5178.66,3803.66 ; v1(3870,4035) 5135,4035 5205,3965 5205,3830 5178.66,3803.66 ; v1(3905,4765) 5205,4765 5315,4655 5415,4655 5560,4510 5560,3760.04 5519.96,3720 5365,3720 ; v1(4630,2325) 4630,2360 4619.41,2370.59 4619.41,2405.16 U20.21@4619.21,2405.36 4619.21,2447.34 4630,2458.13 4630,2470 4790,2630 4990,2630 5100,2740 5100,2810 5075,2835 4950,2835 4920,2865 v1(4920,3290) ; U21.21@5939.21,2405.36 5939.21,2365.79 5965,2340 v1(5965,2325) ; v1(6660,2350) 6050,2960 6050,3165 6900.75,4015.75 U9.21@6900.79,4054.64 U9.21@6900.79,4054.64 ; v1(7270,2360) 7290,2360 7299.5,2369.5 7299.5,2406.48 7287.39,2418.6 7287.39,2421.98 7284.21,2425.16 U8.21@7284.21,2455.36 ; v1(4920,3290) 4920,3355 4955,3390 5010,3390 5260,3640 5325,3640 5365,3680 5365,3720 ; 5178.66,3803.66 5262.32,3720 5365,3720
pads on no net: JTAG1.6 JTAG1.7 JTAG1.8 K1.1 K1.4 K1.5 K1.6 M1. M1.0 M1.0_1 M1.0_2 M1.0_3 M1.J1_1 M1.J1_2 M1.J1_3 M1.J1_4 M1.J1_5 M1.J1_6 M1.J1_7 M1.J1_8 M1.J1_9 M1.J1_10 M1.J1_11 M1.J1_12 M1.J1_13 M1.J1_14 M1.J1_15 M1.J1_16 M1.J1_17 M1.J1_18 M1.J1_19 M1.J1_20 M1.J1_21 M1.J1_22 M1.J1_23 M1.J1_24 M1.J1_25 M1.J1_26 M1.J1_27 M1.J1_28 M1.J1_29 M1.J1_30 M1.J1_31 M1.J1_32 M1.J1_33 M1.J1_34 M1.J1_35 M1.J1_36 M1.J1_37 M1.J1_38 M1.J1_39 M1.J1_40 M1.J1_41 M1.J1_42 M1.J1_43 M1.J1_44 M1.J1_45 M1.J1_46 M1.J1_47 M1.J1_48 M1.J1_49 M1.J1_50 M1.J1_53 M1.J1_54 M1.J1_55 M1.J1_56 M1.J1_57 M1.J1_58 M1.J1_59 M1.J1_60 M1.J2_9 M1.J2_10 M1.J2_21 M1.J2_22 M1.J2_23 M1.J2_24 M1.J2_27 M1.J2_29 M1.J2_30 M1.J2_31 M1.J2_32 M1.J2_33 M1.J2_34 M1.J2_35 M1.J2_36 M1.J2_37 M1.J2_38 M1.J2_39 M1.J2_40 M1.J2_41 M1.J2_42 M1.J2_43 M1.J2_44 M1.J2_45 M1.J2_47 M1.J2_48 M1.J2_49 M1.J2_50 M1.J2_51 M1.J2_52 M1.J2_53 M1.J2_54 M1.J2_55 M1.J2_56 M1.J2_57 M1.J2_58 M1.J2_60 M1.J2_61 M1.J2_65 M1.J2_66 M1.J2_67 M1.J2_68 M1.J2_69 M1.J2_70 M1.J2_71 M1.J2_72 M1.J2_73 M1.J2_74 M1.J2_75 M1.J2_76 M1.J2_77 M1.J2_78 M1.J2_79 M1.J2_80 M1.J3_1 M1.J3_2 M1.J3_3 M1.J3_4 M1.J3_7 M1.J3_8 M1.J3_9 M1.J3_10 M1.J3_13 M1.J3_14 M1.J3_15 M1.J3_16 M1.J3_19 M1.J3_20 M1.J3_21 M1.J3_22 M1.J3_25 M1.J3_26 M1.J3_27 M1.J3_28 M1.J3_34 M1.J3_36 M1.J3_40 M1.J3_41 M1.J3_42 M1.J3_43 M1.J3_44 M1.J3_45 M1.J3_46 M1.J3_47 M1.J3_49 M1.J3_50 M1.J3_51 M1.J3_52 M1.J3_53 M1.J3_54 M1.J3_55 M1.J3_56 M1.J3_57 M1.J3_58 M1.J3_59 M1.J3_60 M1.J4_7 M1.J4_8 M1.J4_9 M1.J4_10 M1.J4_11 M1.J4_12 M1.J4_13 M1.J4_14 M1.J4_15 M1.J4_16 M1.J4_17 M1.J4_18 M1.J4_19 M1.J4_20 M1.J4_21 M1.J4_22 M1.J4_23 M1.J4_24 M1.J4_25 M1.J4_26 M1.J4_27 M1.J4_28 M1.J4_29 M1.J4_30 M1.J4_31 M1.J4_32 M1.J4_33 M1.J4_34 M1.J4_35 M1.J4_36 M1.J4_37 M1.J4_38 M1.J4_39 M1.J4_40 M1.J4_41 M1.J4_42 M1.J4_43 M1.J4_44 M1.J4_45 M1.J4_47 M1.J4_49 M1.J4_50 M1.J4_51 M1.J4_53 M1.J4_55 M1.J4_57 M1.J4_75 M1.J4_77 M1.J4_79 U2.7 U2.8 U2.9 U2.10 U2.11 U2.12 U2.13 U2.14 U2.15 U6.41 U6.42 U6.44 U7.41 U7.42 U7.44 U8.41 U8.42 U8.44 U9.41 U9.42 U9.44 U10.3 U10.9 U11.41 U11.42 U11.44 U12.41 U12.42 U12.44 U20.41 U20.42 U20.44 U21.41 U21.42 U21.44 USB_UART1. USB_UART1.3 USB_UART1.9 X3.39 X3.40 X3.41 X3.42 X3.43 X3.44 X3.45 X6.39 X6.40 X6.41 X6.42 X6.43 X6.44 X6.45
copper on no net: | length 57.7
  Top Layer w15: v1(5285,3285) 5285,3230.49 5285.33,3230.16 5288.03,3230.16

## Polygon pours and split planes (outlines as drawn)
GND on Bottom Layer "NONET_L-01_P-001" (solid, remove dead copper, pour order 2): 851.39,661.21 ccw(c1021.33,666.33) 1016.21,496.39 ccw(c1021.33,505) 1021.33,494.99 7847.92,494.99 ccw(c7847.92,667.08) 8020.02,667.08 8020.02,6107.92 ccw(c7847.92,6107.92) 7847.92,6280.02 1022.08,6280.02 ccw(c1022.08,6107.92) 849.99,6107.92 849.99,666.33 ccw(c860,666.33)
no net on Top Layer "NONET_L-01_P-001" (solid, remove dead copper, pour order 1): 851.39,661.21 ccw(c1021.33,666.33) 1016.21,496.39 ccw(c1021.33,505) 1021.33,494.99 7847.92,494.99 ccw(c7847.92,667.08) 8020.02,667.08 8020.02,6107.92 ccw(c7847.92,6107.92) 7847.92,6280.02 1022.08,6280.02 ccw(c1022.08,6107.92) 849.99,6107.92 849.99,666.33 ccw(c860,666.33)
GND on Top Layer "NONET_L-01_P-001" (solid, remove dead copper, pour order 0): 851.39,661.21 ccw(c1021.33,666.33) 1016.21,496.39 ccw(c1021.33,505) 1021.33,494.99 7847.92,494.99 ccw(c7847.92,667.08) 8020.02,667.08 8020.02,6107.92 ccw(c7847.92,6107.92) 7847.92,6280.02 1022.08,6280.02 ccw(c1022.08,6107.92) 849.99,6107.92 849.99,666.33 ccw(c860,666.33)
+5V on PWR (split plane): 7856.71,6219.66 7865.45,6218.62 7874.08,6216.9 7882.55,6214.52 7890.81,6211.47 7898.8,6207.78 7906.48,6203.48 7913.8,6198.6 7920.71,6193.15 7927.17,6187.17 7933.15,6180.71 7938.6,6173.8 7943.48,6166.48 7947.78,6158.8 7951.47,6150.81 7954.52,6142.55 7956.9,6134.08 7958.62,6125.45 7959.66,6116.71 7959.97,6108.77 7959.92,6107.92 7959.92,667.08 7959.97,666.23 7959.66,658.29 7958.62,649.55 7956.9,640.92 7954.52,632.45 7951.47,624.19 7947.78,616.2 7943.48,608.52 7938.6,601.2 7933.15,594.29 7927.17,587.83 7920.71,581.85 7913.8,576.4 7906.48,571.52 7898.8,567.22 7890.81,563.53 7882.55,560.48 7874.08,558.1 7865.45,556.38 7856.71,555.34 7848.77,555.03 7847.92,555.08 1031.31,555.08 1021.33,559.21 1021.33,556.2 1022.94,556.11 1021.33,556.2 1018.02,556.39 1018.02,556.46 1012.7,556.67 1004.12,557.69 995.65,559.37 987.34,561.72 979.24,564.71 971.39,568.32 963.86,572.54 956.68,577.34 949.89,582.69 943.55,588.55 937.69,594.89 932.34,601.68 927.54,608.86 923.32,616.39 919.71,624.24 916.72,632.34 914.37,640.65 912.69,649.12 911.67,657.7 911.46,663.02 911.39,663.02 911.2,666.33 914.21,666.33 910.08,676.31 910.08,6107.92 910.03,6108.77 910.34,6116.71 911.38,6125.45 913.1,6134.08 915.48,6142.55 918.53,6150.81 922.22,6158.8 926.52,6166.48 931.4,6173.8 936.85,6180.71 942.83,6187.17 949.29,6193.15 956.2,6198.6 963.52,6203.48 971.2,6207.78 979.19,6211.47 987.45,6214.52 995.92,6216.9 1004.55,6218.62 1013.29,6219.66 1021.23,6219.97 1022.08,6219.92 7847.92,6219.92 7848.77,6219.97
+5V on PWR (split plane): 911.2,666.33 911.11,667.94
GND on GND (split plane): 7858.77,6259.62 7869.56,6258.46 7880.25,6256.54 7890.77,6253.85 7901.07,6250.42 7911.1,6246.27 7920.81,6241.41 7930.15,6235.87 7939.06,6229.68 7947.52,6222.86 7955.46,6215.46 7962.86,6207.52 7969.68,6199.06 7975.87,6190.15 7981.41,6180.81 7986.27,6171.1 7990.42,6161.07 7993.85,6150.77 7996.54,6140.25 7998.46,6129.56 7999.62,6118.77 7999.99,6108.62 7999.92,6107.92 7999.92,667.08 7999.99,666.38 7999.62,656.23 7998.46,645.44 7996.54,634.75 7993.85,624.23 7990.42,613.93 7986.27,603.9 7981.41,594.19 7975.87,584.85 7969.68,575.94 7962.86,567.48 7955.46,559.54 7947.52,552.14 7939.06,545.32 7930.15,539.13 7920.81,533.59 7911.1,528.73 7901.07,524.58 7890.77,521.15 7880.25,518.46 7869.56,516.54 7858.77,515.38 7848.62,515.01 7847.92,515.08 1023.5,515.08 1022.91,515.26 1021.33,515.92 1021.33,515.74 1020.13,516.11 1016.81,516.43 1016.81,516.48 1010.63,516.7 999.98,517.85 989.45,519.75 979.07,522.4 968.91,525.78 959.02,529.88 949.44,534.67 940.23,540.14 931.43,546.24 923.1,552.96 915.26,560.26 907.96,568.1 901.24,576.43 895.14,585.23 889.67,594.44 884.88,604.02 880.78,613.91 877.4,624.07 874.75,634.45 872.85,644.98 871.7,655.63 871.48,661.81 871.43,661.81 871.11,665.13 870.74,666.33 870.92,666.33 870.26,667.91 870.08,668.5 870.08,6107.92 870.01,6108.62 870.38,6118.77 871.54,6129.56 873.46,6140.25 876.15,6150.77 879.58,6161.07 883.73,6171.1 888.59,6180.81 894.13,6190.15 900.32,6199.06 907.14,6207.52 914.54,6215.46 922.48,6222.86 930.94,6229.68 939.85,6235.87 949.19,6241.41 958.9,6246.27 968.93,6250.42 979.23,6253.85 989.75,6256.54 1000.44,6258.46 1011.23,6259.62 1021.38,6259.99 1022.08,6259.92 7847.92,6259.92 7848.62,6259.99

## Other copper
Top Layer:
  region net +5V: 4438,5265 4540,5265 4560,5245 4560,5000 4545,4985 4431.7,4985 4418,4998.7 4418,5246.34 4430.17,5258.51
  region net +5V: 5715.5,3064.5 5815.5,3064.5 5830,3050 5830,2975.09 5829.41,2974.5 5813.1,2967 5768,2967 5750,2985 5710.63,2985 5700.5,2995.13 5700.5,3049.5
  region net +5V: 7100,4085 7190,4085 7200,4075 7200,4045 7190,4035 7103.34,4035 7100,4035 7095,4040 7095,4082
  region net +5V: 6995,2460 7075,2460 7085,2450 7085,2425 7075,2415 6995,2415 6985,2425 6985,2450
  region net +5V: 5660,2410 5739.83,2410 5745,2404.83 5745,2368 5742,2365 5655,2365 5645,2375 5645,2400
  region net +5V: 5550,2995 5600,2995 5610,2985 5610,2960 5600,2950 5555,2950 5550,2955
  region net +5V: 5510.41,3119.41 5520.41,3119.41 5547.5,3119.41 5561,3110 5561,2920 5551,2910 5508.84,2910 5496,2922.84 5496,3105
  region net +5V: 5250,2670 5375,2670 5386.59,2658.41 5386.59,2626.65 5379.94,2620 5255,2620 5240,2635 5240,2660
  region net +5V: 4330,2425 4419.49,2425 4419.66,2425.17 4424.83,2420 4425,2420 4425,2395 4420,2390 4330,2390 4325,2395 4325,2420
  region net +5V: 2773,2413 2827,2413 2840,2400 2840,2375 2830,2365 2750,2365 2740,2375 2740,2400 2753,2413
  region net +5V: 2840,3585 2870,3585 2875,3590 2875,3665 2870,3670 2865,3670 2840,3670 2835,3665 2835,3590
  region net +5V: 2844.83,4099.87 2844.96,4100 2880,4100 2885,4105 2885,4185 2875,4195 2845,4195 2837,4187 2837,4107.94
  region net +5V: 2820.09,4844.91 2824.91,4840.09 2859.97,4840.16 2869.91,4850.09 2869.91,4920.09 2859.91,4930.09 2824.91,4930.09 2819.91,4925.09 2819.91,4915.09
Bottom Layer:
  region net VBAT: 3157.74,5710 cw(c3155.37,5729.7) 3135.66,5727.33 3135.66,5831.33 cw(c3152.73,5831.33) 3152.73,5848.4 3183.59,5848.4 cw(c3183.6,5831.33) 3200.66,5831.33 3200.66,5798.4 ccw(c3220.66,5798.4) 3220.66,5778.4 3293.59,5778.4 ccw(c3293.59,5795.47) 3310.66,5795.47 3310.66,5820.66 cw(c3318.4,5820.66) 3318.4,5828.4 3411.74,5828.4 cw(c3411.52,5814.25) 3425.66,5814.25 3425.66,5735.66 cw(c3397.5,5738.16) 3395,5710
  region net NetBattery1_1: 3070,5995 cw(c3070,6005) 3060,6005 3060,6185 cw(c3085,6185) 3085,6210 3155,6210 cw(c3155,6195) 3170,6195 3170,6080 ccw(c3185,6080) 3185,6065 3305,6065 cw(c3305,6050) 3320,6050 3320,5985 cw(c3305,5985) 3305,5970 3230,5970 cw(c3230,5985) 3215,5985 ccw(c3205,5985) 3205,5995
  region net VBTN: 4334.73,5640.34 4334.73,5739.73 cw(c4355,5739.73) 4355,5760 4415,5760 ccw(c4415,5770) 4425,5770 4425,5880 ccw(c4420,5880) 4420,5885 4395,5885 cw(c4395,5905) 4375,5905 4375,5930 cw(c4390,5930) 4390,5945 4435,5945 cw(c4435,5925) 4455,5925 4455,5885 ccw(c4460,5885) 4460,5880 4470,5880 cw(c4470,5875) 4475,5875 4475,5730 ccw(c4505,5730) 4505,5700 4520,5700 ccw(c4520,5715) 4535,5715 4535,5754.64 cw(c4620.36,5754.64) 4620.36,5840 4705,5840 ccw(c4705,5850) 4715,5850 4715,5902.93 cw(c4732.07,5902.93) 4732.07,5920 4810,5920 cw(c4810,5905) 4825,5905 4825,5830 cw(c4780,5830) 4780,5785 4635.36,5785 ccw(c4635.36,5739.64) 4590,5739.64 4590,5630 cw(c4565,5630) 4565,5605 4370.07,5605 cw(c4370.07,5640.34)
  region net NetC12_2: 4120.14,6065 4180,6065 cw(c4180,6060) 4185,6060 4185,5940 ccw(c4190,5940) 4190,5935 4290,5935 ccw(c4290,5945) 4300,5945 4300,5990 cw(c4310,5990) 4310,6000 4525,6000 ccw(c4525,6025) 4550,6025 4550,6055 ccw(c4535,6055) 4535,6070 4494.96,6070 ccw(c4495,6060) 4485,6060 4485,6030 cw(c4480,6030) 4480,6025 4285,6025 cw(c4285,6044.73) 4265.27,6044.73 4265.27,6114.66 ccw(c4254.93,6114.66) 4254.93,6125 4185,6125 cw(c4185,6145) 4165,6145 4165,6165 ccw(c4140,6165) 4140,6190 4125,6190 ccw(c4124.04,6176.23) 4110.27,6177.18 4110.27,6074.87 ccw(c4120.14,6074.87)
  region net NetD1_1: 3690,5760 3690,5805 cw(c3725,5805) 3725,5840 3950,5840 ccw(c3950,5890) 4000,5890 4000,6015 cw(c4025,6015) 4025,6040 4095,6040 cw(c4095,6015) 4120,6015 4120,5775 cw(c4070,5775) 4070,5725 3725,5725 cw(c3725,5760)
  region net +3.3V: 4705,4255 4715,4255 4985,4255 4995,4245 4995,4182.5 4982.5,4170 4705,4170 4695,4180 4695,4247.5
  region net +5V: 2910,5730 3025,5730 3035,5720 3035,5655 3020,5640 2945,5640 2935,5630 2935,5525 2955,5505 3000,5505 3010,5495 3010,5445 2990,5425 2917.9,5425 2880,5462.9 2880,5700
  region net +5V: 2733,2375 2743,2365 2895,2365 2904,2375 2904,2440 2898,2445 2863,2445 2858,2440 2858,2421 2850,2413 2746,2413 2733,2400
  region net +5V: 7044.43,4012.65 7183.35,4012.65 7200.59,4029.88 7200.59,4079.59 7183.54,4096.64 7041.64,4096.64 7031,4086 7031,4020
  region net +5V: 6999,2460 7103,2459 7114,2470 7114,2488.45 7114,2495 7120.06,2500.27 7143.73,2500.27 7154,2490 7154,2425 7144,2415 6995.24,2415 6989,2421.82 6989,2455
  region net +5V: 5654.4,2415.4 5762.6,2415.4 5763,2415 5773,2425 5773,2444.36 5779.73,2451.09 5779.83,2450.99 5802.01,2450.99 5808,2445 5808,2371.85 5800,2365 5790,2365 5793,2365 5788,2365 5655.12,2362.88 5643,2375 5643,2407.81
  region net +5V: 5250,2670 5375,2670 5386.59,2658.41 5421.59,2658.41 5425.17,2654.83 5425.17,2604.87 5420.3,2600 5383,2600 5379.94,2603.06 5379.94,2620 5255,2620 5240,2635 5240,2660
  region net +5V: 4334.05,2426.73 4443,2425.69 4454.05,2436.73 4454.05,2446.1 4460.78,2452.83 4460.88,2452.72 4483.06,2452.72 4489.05,2446.73 4489.05,2374.05 4480.25,2365.25 4452.48,2364.8 4429.55,2387.73 4333.05,2387.73 4324.05,2396.73 4324.05,2421.73
  region net +5V: 2842,3666.11 2906.66,3666.11 2912.76,3660 2912.76,3641.93 2919.69,3635 2937.76,3635 2942.76,3630 2942.76,3560 2932.76,3550 2907.76,3550 2898.78,3558.98 2898.78,3626.69 2890.47,3635 2852.98,3635 2840.89,3635 2836.66,3639.24 2836.66,3660.76
  region net +5V: 2860.22,4199 2915,4199 2934,4180 2934,4085 2928.38,4079.38 2891.12,4079.38 2882.61,4087.89 2882.61,4156.39 2875.11,4163.89 2853.24,4163.89 2847.89,4169.24 2847.89,4190.76
  region net +5V: 2847.22,4931.92 2924.09,4931.92 2925.09,4932.92 2931.75,4926.25 2931.75,4824.58 2925.91,4818.74 2899.06,4818.74 2891,4826.8 2891,4893.2 2886.28,4897.92 2845.43,4897.92 2836.09,4905.05 2836.09,4920.79

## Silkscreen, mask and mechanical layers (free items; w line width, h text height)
Mechanical 1:
  lines w20: 860,666.33 860,6107.92 cw(c1022.08,6107.92) 1022.08,6270 2140,6270 7847.92,6270 cw(c7847.92,6107.92) 8010,6107.92 8010,667.08 cw(c7847.92,667.08) 7847.92,505 1021.33,505 ; 861.33,666.33 ccw(c1021.33,666.33) 1021.33,506.33 ; 5425,0 5435,0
